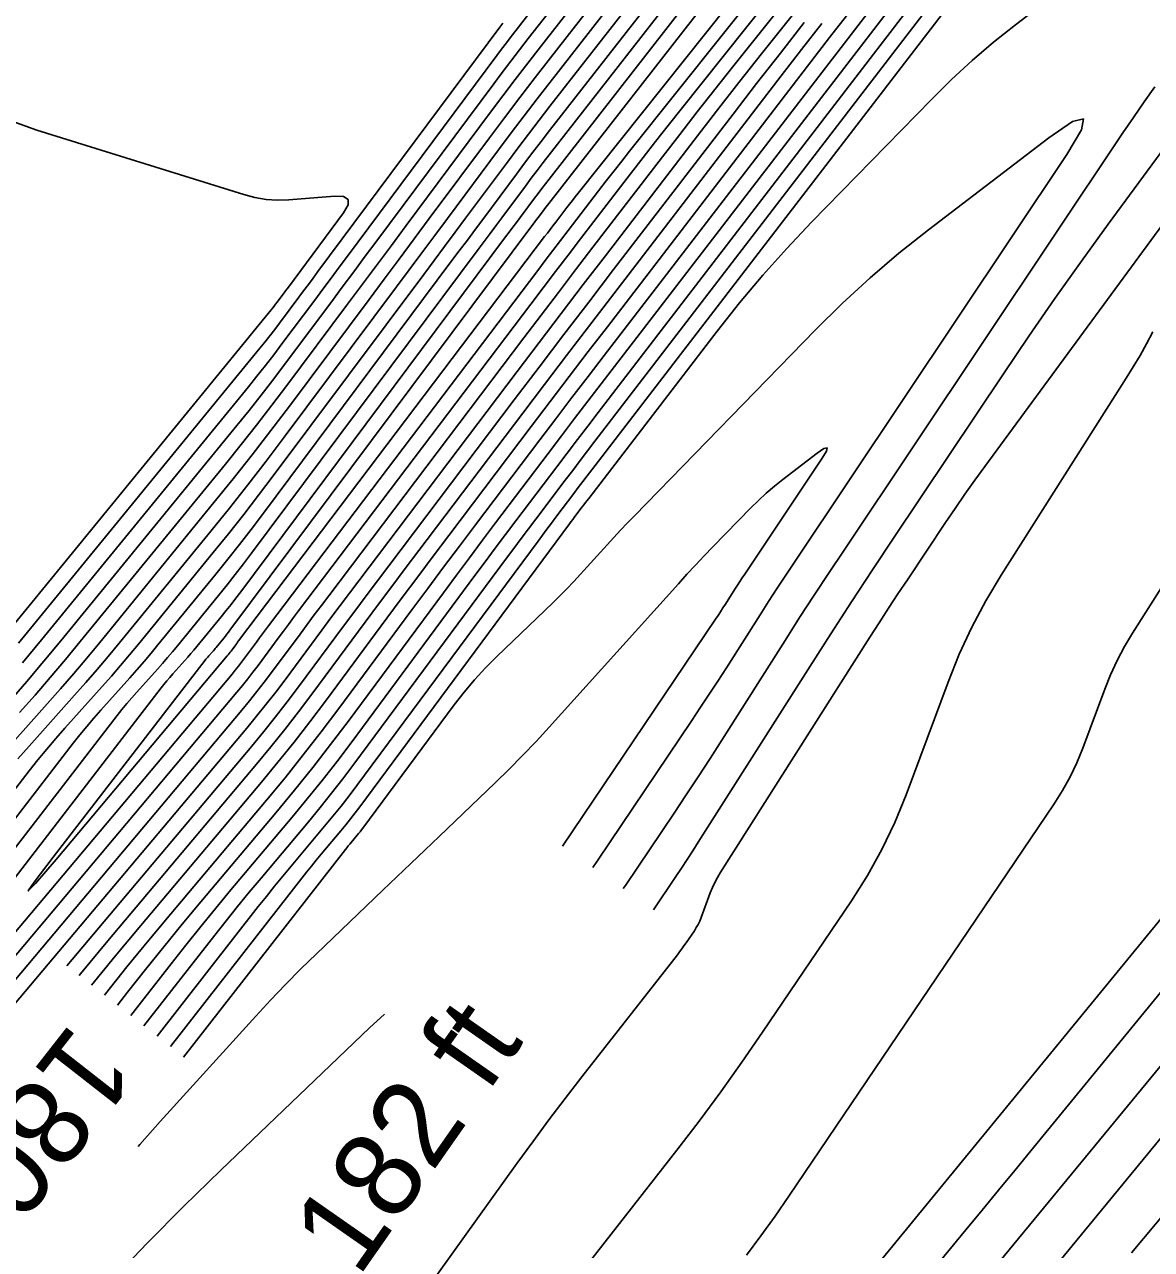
# Model space of a CAD drawing. Extents: x 7585033 to 7595090, y 547091 to 553471.
# Drawn here: x 7587377.6 to 7587459.7, y 548541.5 to 548630.8 of the extents above; entities that cross this region are included whole.
import ezdxf

# ---------------------------------------------------------------- set-up
doc = ezdxf.new("R2010")
doc.units = 0
for name, color, linetype in [('E_TERR_DSPLAY_GeneralTx', 7, 'Continuous'), ('E_TERR_DSPLAY_MajContour', 7, 'Continuous'), ('E_TERR_DSPLAY_MinContour', 7, 'Continuous')]:
    doc.layers.add(name, color=color, linetype=linetype)

msp = doc.modelspace()

# ---------------------------------------------------------------- linework, layer by layer
at = {"layer": 'E_TERR_DSPLAY_MajContour'}
for points in [[(7587442.537, 548646.082), (7587425.414, 548624.598), (7587424.486, 548623.428), (7587423.563, 548622.254), (7587422.646, 548621.076), (7587421.733, 548619.894), (7587418.096, 548615.158), (7587417.187, 548613.973), (7587416.281, 548612.786), (7587415.377, 548611.598), (7587414.475, 548610.408), (7587397.571, 548588.065), (7587397.199, 548587.571), (7587396.827, 548587.076), (7587396.457, 548586.58), (7587396.088, 548586.083), (7587394.615, 548584.094), (7587394.243, 548583.6), (7587393.863, 548583.112), (7587393.476, 548582.629), (7587393.082, 548582.153), (7587370.08, 548554.8)], [(7587365.047, 548555.381), (7587384.36, 548580.435), (7587384.705, 548580.875), (7587385.059, 548581.308), (7587385.421, 548581.735), (7587385.79, 548582.155), (7587387.284, 548583.822), (7587387.655, 548584.241), (7587388.021, 548584.664), (7587388.383, 548585.091), (7587388.739, 548585.523), (7587391.74, 548589.193), (7587392.354, 548589.953), (7587392.959, 548590.719), (7587393.556, 548591.492), (7587394.145, 548592.271), (7587410.651, 548614.388), (7587411.08, 548614.964), (7587411.509, 548615.54), (7587411.938, 548616.116), (7587412.367, 548616.691), (7587414.082, 548618.996), (7587414.512, 548619.57), (7587414.946, 548620.143), (7587415.382, 548620.713), (7587415.822, 548621.28), (7587432.364, 548642.5)], [(7587446.767, 548638.177), (7587419.37, 548602.506), (7587418.616, 548601.522), (7587417.864, 548600.538), (7587417.113, 548599.551), (7587416.365, 548598.564), (7587413.374, 548594.611), (7587412.628, 548593.622), (7587411.884, 548592.631), (7587411.143, 548591.638), (7587410.404, 548590.643), (7587401.384, 548578.463), (7587400.344, 548577.081), (7587399.283, 548575.716), (7587398.201, 548574.367), (7587397.098, 548573.035), (7587392.644, 548567.739), (7587391.537, 548566.41), (7587390.442, 548565.071), (7587389.359, 548563.722), (7587388.289, 548562.362), (7587385.341, 548558.581)], [(7587420.861, 548634.706), (7587415.908, 548628.353), (7587414.785, 548626.903), (7587413.669, 548625.447), (7587412.562, 548623.985), (7587411.463, 548622.517), (7587407.083, 548616.632), (7587405.988, 548615.161), (7587404.892, 548613.69), (7587403.796, 548612.219), (7587402.699, 548610.749), (7587396.894, 548602.972), (7587395.552, 548601.193), (7587394.19, 548599.43), (7587392.808, 548597.681), (7587391.407, 548595.948), (7587383.083, 548585.765), (7587382.145, 548584.63), (7587381.194, 548583.506), (7587380.231, 548582.394), (7587379.255, 548581.292), (7587375.325, 548576.906)], [(7587377.181, 548585.706), (7587394.741, 548607.188), (7587395.108, 548607.643), (7587395.47, 548608.101), (7587395.827, 548608.563), (7587396.179, 548609.03), (7587397.577, 548610.902), (7587397.926, 548611.371), (7587398.276, 548611.839), (7587398.625, 548612.307), (7587398.973, 548612.776), (7587412.226, 548630.583), (7587412.296, 548630.677), (7587412.367, 548630.771), (7587412.439, 548630.865)], [(7587381.589, 548561.515), (7587381.682, 548561.628), (7587383.689, 548564.037), (7587394.506, 548576.9), (7587395.544, 548578.153), (7587396.562, 548579.422), (7587397.56, 548580.707), (7587398.539, 548582.008), (7587402.414, 548587.24), (7587403.385, 548588.547), (7587404.359, 548589.851), (7587405.336, 548591.153), (7587406.316, 548592.452), (7587413.889, 548602.463), (7587415.481, 548604.562), (7587417.076, 548606.659), (7587418.675, 548608.753), (7587420.278, 548610.844), (7587432.711, 548627.031), (7587434.186, 548628.943), (7587435.67, 548630.848)], [(7587389.192, 548555.57), (7587400.975, 548570.679), (7587401.079, 548570.812), (7587401.184, 548570.943), (7587401.29, 548571.073), (7587401.398, 548571.202), (7587401.831, 548571.717), (7587401.938, 548571.847), (7587402.043, 548571.978), (7587402.147, 548572.11), (7587402.248, 548572.245), (7587408.887, 548581.21), (7587409.61, 548582.144), (7587410.37, 548583.045), (7587411.168, 548583.912), (7587412.003, 548584.747), (7587416.082, 548588.655), (7587416.599, 548589.161), (7587417.108, 548589.675), (7587417.606, 548590.199), (7587418.096, 548590.733), (7587420.033, 548592.885), (7587420.52, 548593.42), (7587421.012, 548593.951), (7587421.51, 548594.476), (7587422.012, 548594.997), (7587435.197, 548608.523), (7587437.155, 548610.46), (7587439.179, 548612.323), (7587441.27, 548614.111), (7587443.427, 548615.825), (7587452.186, 548622.53), (7587453.91, 548623.711), (7587454.704, 548623.899), (7587454.567, 548623.094), (7587453.5, 548621.298), (7587433.665, 548591.621), (7587433.031, 548590.668), (7587432.404, 548589.711), (7587431.782, 548588.75), (7587431.165, 548587.785), (7587428.711, 548583.919), (7587428.094, 548582.955), (7587427.471, 548581.995), (7587426.841, 548581.039), (7587426.205, 548580.087), (7587419.349, 548569.903), (7587418.994, 548569.38)], [(7587408.666, 548527.763), (7587425.109, 548548.79), (7587426.725, 548550.894), (7587428.305, 548553.026), (7587429.847, 548555.185), (7587431.352, 548557.37), (7587437.821, 548566.938), (7587438.989, 548568.781), (7587440.041, 548570.684), (7587440.978, 548572.647), (7587441.799, 548574.669), (7587444.85, 548582.877), (7587445.664, 548584.903), (7587446.581, 548586.879), (7587447.601, 548588.803), (7587448.723, 548590.677), (7587457.821, 548605.008), (7587458.335, 548605.837), (7587458.832, 548606.676), (7587459.312, 548607.525), (7587459.774, 548608.385)], [(7587465.377, 548566.427), (7587450.887, 548548.741), (7587449.706, 548547.301), (7587448.525, 548545.862), (7587447.343, 548544.423), (7587446.16, 548542.985), (7587440.861, 548536.55)]]:
    msp.add_lwpolyline(points, dxfattribs=at)
at = {"layer": 'E_TERR_DSPLAY_MinContour'}
for points in [[(7587438.397, 548646.757), (7587415.779, 548617.744), (7587415.681, 548617.618), (7587415.584, 548617.491), (7587415.487, 548617.363), (7587415.392, 548617.235), (7587415.009, 548616.721), (7587414.914, 548616.593), (7587414.818, 548616.465), (7587414.722, 548616.336), (7587414.627, 548616.208), (7587392.566, 548586.648), (7587392.457, 548586.504), (7587392.347, 548586.362), (7587392.235, 548586.22), (7587392.122, 548586.08), (7587391.568, 548585.402), (7587391.502, 548585.322), (7587391.435, 548585.243), (7587391.367, 548585.165), (7587391.299, 548585.087), (7587391.023, 548584.779), (7587390.954, 548584.702), (7587390.888, 548584.623), (7587390.822, 548584.543), (7587390.758, 548584.462), (7587379.703, 548570.119), (7587378.317, 548568.296), (7587377.889, 548567.661), (7587378.418, 548568.214), (7587379.905, 548569.956), (7587392.37, 548584.779), (7587392.443, 548584.867), (7587392.514, 548584.956), (7587392.584, 548585.046), (7587392.653, 548585.138), (7587392.925, 548585.505), (7587392.993, 548585.597), (7587393.062, 548585.689), (7587393.13, 548585.78), (7587393.199, 548585.871), (7587415.479, 548615.321), (7587415.68, 548615.586), (7587415.882, 548615.851), (7587416.084, 548616.115), (7587416.286, 548616.379), (7587417.097, 548617.435), (7587417.3, 548617.699), (7587417.505, 548617.961), (7587417.71, 548618.223), (7587417.917, 548618.483), (7587441.253, 548647.763)], [(7587441.895, 548646.922), (7587421.665, 548621.541), (7587421.098, 548620.825), (7587420.534, 548620.108), (7587419.973, 548619.388), (7587419.415, 548618.665), (7587417.191, 548615.769), (7587416.635, 548615.044), (7587416.081, 548614.319), (7587415.528, 548613.592), (7587414.977, 548612.864), (7587395.385, 548586.968), (7587395.165, 548586.675), (7587394.944, 548586.382), (7587394.725, 548586.089), (7587394.507, 548585.794), (7587393.634, 548584.616), (7587393.414, 548584.323), (7587393.189, 548584.034), (7587392.96, 548583.748), (7587392.726, 548583.466), (7587366.678, 548552.491)], [(7587373.482, 548557.109), (7587393.438, 548580.839), (7587393.993, 548581.51), (7587394.538, 548582.189), (7587395.072, 548582.877), (7587395.596, 548583.573), (7587397.67, 548586.373), (7587398.189, 548587.072), (7587398.71, 548587.77), (7587399.233, 548588.466), (7587399.758, 548589.162), (7587413.973, 548607.951), (7587415.225, 548609.604), (7587416.481, 548611.254), (7587417.739, 548612.901), (7587419, 548614.547), (7587424.052, 548621.124), (7587425.318, 548622.765), (7587426.592, 548624.401), (7587427.873, 548626.031), (7587429.162, 548627.655), (7587443.179, 548645.242)], [(7587364.647, 548552.726), (7587387.559, 548582.448), (7587387.764, 548582.709), (7587387.973, 548582.965), (7587388.188, 548583.218), (7587388.406, 548583.467), (7587389.291, 548584.455), (7587389.511, 548584.703), (7587389.728, 548584.954), (7587389.942, 548585.207), (7587390.153, 548585.462), (7587391.931, 548587.637), (7587392.295, 548588.086), (7587392.653, 548588.54), (7587393.007, 548588.998), (7587393.355, 548589.46), (7587412.639, 548615.298), (7587412.901, 548615.65), (7587413.164, 548616.002), (7587413.426, 548616.354), (7587413.688, 548616.706), (7587414.737, 548618.115), (7587415, 548618.467), (7587415.265, 548618.817), (7587415.532, 548619.165), (7587415.801, 548619.512), (7587435.381, 548644.628)], [(7587376.884, 548559.419), (7587393.794, 548579.526), (7587394.51, 548580.391), (7587395.213, 548581.267), (7587395.902, 548582.154), (7587396.577, 548583.051), (7587399.251, 548586.662), (7587399.921, 548587.564), (7587400.593, 548588.464), (7587401.267, 548589.362), (7587401.944, 548590.259), (7587413.471, 548605.495), (7587415.073, 548607.61), (7587416.68, 548609.721), (7587418.291, 548611.83), (7587419.905, 548613.936), (7587426.37, 548622.353), (7587427.991, 548624.454), (7587429.621, 548626.548), (7587431.261, 548628.634), (7587432.91, 548630.712), (7587443.821, 548644.401)], [(7587387.266, 548557.076), (7587394.632, 548566.521), (7587395.219, 548567.267), (7587395.813, 548568.007), (7587396.413, 548568.741), (7587397.021, 548569.47), (7587399.464, 548572.376), (7587400.069, 548573.107), (7587400.663, 548573.847), (7587401.245, 548574.596), (7587401.816, 548575.354), (7587414.998, 548593.153), (7587415.321, 548593.588), (7587415.645, 548594.022), (7587415.97, 548594.455), (7587416.296, 548594.887), (7587417.603, 548596.614), (7587417.93, 548597.046), (7587418.258, 548597.477), (7587418.586, 548597.907), (7587418.916, 548598.337), (7587453.795, 548643.75)], [(7587450.281, 548640.964), (7587419.143, 548600.421), (7587418.601, 548599.715), (7587418.061, 548599.007), (7587417.522, 548598.299), (7587416.984, 548597.589), (7587414.835, 548594.749), (7587414.299, 548594.038), (7587413.764, 548593.326), (7587413.232, 548592.613), (7587412.701, 548591.898), (7587401.6, 548576.909), (7587400.794, 548575.839), (7587399.973, 548574.781), (7587399.135, 548573.737), (7587398.281, 548572.705), (7587394.832, 548568.605), (7587393.975, 548567.576), (7587393.127, 548566.539), (7587392.289, 548565.494), (7587391.461, 548564.442), (7587386.303, 548557.829)], [(7587429.348, 548640.371), (7587415.844, 548623.048), (7587415.233, 548622.26), (7587414.627, 548621.469), (7587414.025, 548620.674), (7587413.427, 548619.876), (7587411.046, 548616.677), (7587410.451, 548615.877), (7587409.855, 548615.077), (7587409.259, 548614.278), (7587408.663, 548613.479), (7587394.934, 548595.083), (7587394.106, 548593.986), (7587393.265, 548592.898), (7587392.413, 548591.819), (7587391.549, 548590.75), (7587387.325, 548585.583), (7587386.823, 548584.976), (7587386.315, 548584.375), (7587385.799, 548583.779), (7587385.277, 548583.19), (7587383.174, 548580.843), (7587382.654, 548580.251), (7587382.145, 548579.651), (7587381.647, 548579.041), (7587381.16, 548578.421), (7587365.447, 548558.037)], [(7587426.332, 548638.242), (7587415.865, 548624.817), (7587415.084, 548623.808), (7587414.307, 548622.795), (7587413.537, 548621.778), (7587412.772, 548620.756), (7587409.725, 548616.662), (7587408.963, 548615.638), (7587408.201, 548614.615), (7587407.438, 548613.592), (7587406.675, 548612.569), (7587395.723, 548597.895), (7587394.655, 548596.48), (7587393.572, 548595.077), (7587392.473, 548593.686), (7587391.358, 548592.307), (7587385.911, 548585.644), (7587385.264, 548584.861), (7587384.608, 548584.085), (7587383.943, 548583.317), (7587383.269, 548582.557), (7587380.558, 548579.53), (7587379.887, 548578.768), (7587379.231, 548577.993), (7587378.589, 548577.206), (7587377.961, 548576.408), (7587365.847, 548560.692)], [(7587458.093, 548637.129), (7587449.775, 548630.761), (7587448.167, 548629.484), (7587446.609, 548628.15), (7587445.099, 548626.762), (7587443.64, 548625.317), (7587434.916, 548616.368), (7587433.112, 548614.462), (7587431.367, 548612.506), (7587429.679, 548610.499), (7587428.051, 548608.442), (7587418.689, 548596.253), (7587418.572, 548596.1), (7587418.455, 548595.947), (7587418.338, 548595.793), (7587418.222, 548595.64), (7587417.757, 548595.025), (7587417.641, 548594.871), (7587417.525, 548594.717), (7587417.41, 548594.563), (7587417.295, 548594.408), (7587402.032, 548573.799), (7587401.696, 548573.353), (7587401.353, 548572.912), (7587401.004, 548572.477), (7587400.648, 548572.046), (7587399.209, 548570.336), (7587398.852, 548569.907), (7587398.498, 548569.475), (7587398.149, 548569.039), (7587397.803, 548568.6), (7587388.229, 548556.323)], [(7587377.12, 548577.284), (7587377.941, 548578.218), (7587381.262, 548581.924), (7587382.087, 548582.856), (7587382.901, 548583.796), (7587383.705, 548584.745), (7587384.497, 548585.704), (7587391.167, 548593.864), (7587392.532, 548595.552), (7587393.878, 548597.256), (7587395.205, 548598.974), (7587396.513, 548600.706), (7587404.687, 548611.659), (7587405.617, 548612.906), (7587406.546, 548614.152), (7587407.475, 548615.399), (7587408.404, 548616.647), (7587412.118, 548621.637), (7587413.05, 548622.882), (7587413.988, 548624.121), (7587414.934, 548625.356), (7587415.887, 548626.585), (7587423.315, 548636.114)], [(7587443.253, 548635.391), (7587419.597, 548604.59), (7587418.631, 548603.33), (7587417.667, 548602.068), (7587416.705, 548600.804), (7587415.746, 548599.539), (7587411.913, 548594.473), (7587410.957, 548593.205), (7587410.004, 548591.935), (7587409.054, 548590.662), (7587408.107, 548589.387), (7587401.168, 548580.018), (7587399.893, 548578.324), (7587398.592, 548576.651), (7587397.266, 548574.997), (7587395.914, 548573.364), (7587390.455, 548566.873), (7587389.098, 548565.244), (7587387.756, 548563.603), (7587386.429, 548561.949), (7587385.118, 548560.283), (7587384.378, 548559.334)], [(7587418.846, 548633.862), (7587415.169, 548629.146), (7587414.254, 548627.964), (7587413.345, 548626.778), (7587412.442, 548625.586), (7587411.546, 548624.389), (7587405.409, 548616.143), (7587404.324, 548614.685), (7587403.238, 548613.227), (7587402.151, 548611.77), (7587401.064, 548610.313), (7587396.716, 548604.486), (7587395.621, 548603.036), (7587394.51, 548601.598), (7587393.383, 548600.172), (7587392.241, 548598.758), (7587381.669, 548585.825), (7587380.586, 548584.515), (7587379.488, 548583.217), (7587378.375, 548581.932), (7587377.248, 548580.659)], [(7587416.831, 548633.018), (7587414.283, 548629.75), (7587413.649, 548628.931), (7587413.019, 548628.109), (7587412.393, 548627.283), (7587411.773, 548626.454), (7587403.264, 548615.021), (7587402.424, 548613.892), (7587401.584, 548612.764), (7587400.743, 548611.637), (7587399.902, 548610.509), (7587396.537, 548606.001), (7587395.69, 548604.878), (7587394.83, 548603.765), (7587393.958, 548602.662), (7587393.074, 548601.568), (7587380.255, 548585.886), (7587379.026, 548584.4), (7587377.781, 548582.928), (7587376.519, 548581.47)], [(7587377.467, 548584.284), (7587378.841, 548585.946), (7587393.908, 548604.378), (7587394.533, 548605.152), (7587395.15, 548605.933), (7587395.758, 548606.721), (7587396.358, 548607.515), (7587398.739, 548610.706), (7587399.335, 548611.504), (7587399.93, 548612.302), (7587400.524, 548613.1), (7587401.119, 548613.898), (7587411.999, 548628.518), (7587412.345, 548628.98), (7587412.693, 548629.44), (7587413.044, 548629.898), (7587413.397, 548630.354), (7587414.816, 548632.174)], [(7587383.424, 548560.08), (7587383.5, 548560.177), (7587385.071, 548562.135), (7587386.66, 548564.078), (7587388.267, 548566.007), (7587395.218, 548574.273), (7587396.578, 548575.915), (7587397.911, 548577.578), (7587399.219, 548579.261), (7587400.501, 548580.964), (7587405.81, 548588.132), (7587406.965, 548589.687), (7587408.123, 548591.239), (7587409.286, 548592.788), (7587410.453, 548594.335), (7587415.127, 548600.513), (7587416.297, 548602.057), (7587417.47, 548603.598), (7587418.646, 548605.138), (7587419.824, 548606.675), (7587439.739, 548632.604)], [(7587382.498, 548560.804), (7587384.221, 548562.912), (7587386.078, 548565.141), (7587394.862, 548575.586), (7587396.061, 548577.034), (7587397.237, 548578.5), (7587398.39, 548579.984), (7587399.52, 548581.486), (7587403.996, 548587.529), (7587405.117, 548589.038), (7587406.241, 548590.545), (7587407.37, 548592.049), (7587408.502, 548593.549), (7587414.508, 548601.488), (7587415.889, 548603.31), (7587417.273, 548605.129), (7587418.66, 548606.945), (7587420.051, 548608.759), (7587436.225, 548629.818), (7587437.455, 548631.412)], [(7587434.388, 548630.91), (7587432.647, 548628.696), (7587430.917, 548626.475), (7587429.197, 548624.245), (7587420.505, 548612.928), (7587418.69, 548610.561), (7587416.879, 548608.189), (7587415.073, 548605.815), (7587413.27, 548603.437), (7587404.13, 548591.356), (7587403.301, 548590.258), (7587402.476, 548589.157), (7587401.653, 548588.055), (7587400.833, 548586.951), (7587397.558, 548582.529), (7587396.731, 548581.43), (7587395.887, 548580.345), (7587395.027, 548579.272), (7587394.15, 548578.213), (7587380.695, 548562.214)], [(7587395.207, 548522.349), (7587413.463, 548547.804), (7587414.62, 548549.4), (7587415.794, 548550.984), (7587416.984, 548552.555), (7587418.19, 548554.115), (7587425.146, 548563.01), (7587425.31, 548563.223), (7587425.47, 548563.439), (7587425.627, 548563.658), (7587425.779, 548563.88), (7587426.382, 548564.771), (7587426.526, 548564.998), (7587426.655, 548565.232), (7587426.77, 548565.473), (7587426.871, 548565.722), (7587427.542, 548567.527), (7587427.695, 548567.907), (7587427.867, 548568.278), (7587428.058, 548568.639), (7587428.269, 548568.99), (7587439.161, 548586.148), (7587439.834, 548587.201), (7587440.514, 548588.25), (7587441.199, 548589.295), (7587441.89, 548590.336), (7587444.669, 548594.493), (7587445.369, 548595.529), (7587446.08, 548596.556), (7587446.803, 548597.576), (7587447.537, 548598.587), (7587469.682, 548628.767)], [(7587464.757, 548627.455), (7587456.514, 548616.221), (7587454.562, 548613.53), (7587452.639, 548610.818), (7587450.747, 548608.085), (7587448.884, 548605.331), (7587440.891, 548593.371), (7587439.351, 548591.054), (7587437.826, 548588.727), (7587436.314, 548586.391), (7587434.816, 548584.047), (7587426.667, 548571.212), (7587426.265, 548570.584), (7587425.859, 548569.958), (7587425.449, 548569.335), (7587425.034, 548568.715), (7587423.406, 548566.297)], [(7587421.2, 548567.838), (7587421.358, 548568.071), (7587424.903, 548573.337), (7587425.785, 548574.656), (7587426.658, 548575.981), (7587427.522, 548577.312), (7587428.377, 548578.649), (7587432.991, 548585.916), (7587434.048, 548587.57), (7587435.115, 548589.219), (7587436.191, 548590.861), (7587437.278, 548592.496), (7587457.587, 548622.882), (7587458.35, 548624.01), (7587459.126, 548625.13), (7587459.913, 548626.241)], [(7587376.143, 548623.935), (7587378.52, 548623.085), (7587393.583, 548618.38), (7587394.385, 548618.17), (7587395.195, 548618.039), (7587396.015, 548617.985), (7587396.844, 548618.009), (7587400.175, 548618.263), (7587400.842, 548618.235), (7587401.175, 548618.023), (7587401.176, 548617.628), (7587400.844, 548617.05), (7587396.828, 548611.654), (7587396.725, 548611.515), (7587396.622, 548611.376), (7587396.518, 548611.237), (7587396.415, 548611.099), (7587396.001, 548610.544), (7587395.896, 548610.406), (7587395.79, 548610.269), (7587395.683, 548610.133), (7587395.574, 548609.999), (7587374.125, 548583.758)], [(7587430.18, 548541.128), (7587431.231, 548542.546), (7587432.257, 548543.982), (7587433.259, 548545.437), (7587452.579, 548574.014), (7587453.19, 548574.979), (7587453.741, 548575.975), (7587454.231, 548577.002), (7587454.661, 548578.06), (7587456.258, 548582.356), (7587456.684, 548583.417), (7587457.164, 548584.451), (7587457.698, 548585.458), (7587458.285, 548586.439), (7587472.904, 548609.467)], [(7587385.892, 548549.059), (7587386, 548549.185), (7587387.499, 548550.869), (7587394.454, 548558.542), (7587395.53, 548559.708), (7587396.625, 548560.854), (7587397.741, 548561.981), (7587398.877, 548563.088), (7587403.708, 548567.715), (7587404.729, 548568.693), (7587405.75, 548569.671), (7587406.772, 548570.649), (7587407.793, 548571.628), (7587411.877, 548575.541), (7587412.888, 548576.528), (7587413.881, 548577.534), (7587414.856, 548578.558), (7587415.811, 548579.6), (7587425.216, 548590.045), (7587425.835, 548590.726), (7587426.46, 548591.4), (7587427.092, 548592.068), (7587427.731, 548592.73), (7587430.488, 548595.558), (7587431.046, 548596.11), (7587431.622, 548596.64), (7587432.217, 548597.149), (7587432.831, 548597.637), (7587435.325, 548599.546), (7587435.816, 548599.882), (7587436.042, 548599.936), (7587436.003, 548599.707), (7587435.699, 548599.195), (7587430.052, 548590.747), (7587429.872, 548590.475), (7587429.693, 548590.203), (7587429.516, 548589.929), (7587429.34, 548589.654), (7587428.642, 548588.554), (7587428.466, 548588.279), (7587428.289, 548588.006), (7587428.109, 548587.734), (7587427.928, 548587.463), (7587416.791, 548570.92)], [(7587467.002, 548573.747), (7587440.059, 548540.86)], [(7587403.83, 548558.679), (7587402.736, 548557.702), (7587391.894, 548547.318), (7587389.208, 548544.699), (7587386.568, 548542.034), (7587383.977, 548539.323)], [(7587450.287, 548537.44), (7587466.934, 548557.659)], [(7587460.632, 548555.3), (7587459.273, 548553.642), (7587457.913, 548551.986), (7587456.553, 548550.33), (7587455.191, 548548.675), (7587445.574, 548536.995)], [(7587465.072, 548549.503), (7587458.219, 548541.312)]]:
    msp.add_lwpolyline(points, dxfattribs=at)

# ---------------------------------------------------------------- texts
at = {"layer": 'E_TERR_DSPLAY_GeneralTx'}
for s, rotation, p in [('182 ft', 55.05441, (7587401.907, 548539.429)), ('180 ft', 231.97605, (7587381.063, 548558.224))]:
    msp.add_text(s, height=6.3, rotation=rotation, dxfattribs=at).set_placement(p)

doc.saveas('drawing.dxf')
